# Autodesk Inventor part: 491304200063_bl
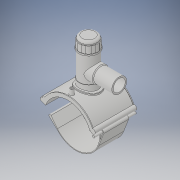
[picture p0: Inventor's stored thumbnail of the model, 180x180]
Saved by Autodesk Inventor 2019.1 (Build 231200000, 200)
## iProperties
Created: 2017-07
Part Number: 491304200063_bl
Material: Generic
Description: PLASSON TAPPING TEE SADDLE 200mm x 63mm
Document SubType Name: Modeling
Designer: KIM
Mass: 1712.7 g
Surface Area: 2671.49 cm^2
Volume: 1712.7 cm^3
Density: 1 g/cm^3
Appearance: Default
Author: KIM
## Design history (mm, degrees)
derived "491304.ipt"
feature "Solid1::491304.ipt" dims "ScaleForDerivedMember" = 10
feature "Solid2::491304.ipt" dims "ScaleForDerivedMember" = 10
feature "Solid4::491304.ipt" dims "ScaleForDerivedMember" = 10
feature "Solid5::491304.ipt" dims "ScaleForDerivedMember" = 10
tag "TaggingFeature1"
body "Solid1"
body "Solid2"
other parameters: "d1" = 101.118 [user parameter], "d2" = 284.8 [user parameter], "d4" = 176 [user parameter], "d5" = 0 [user parameter], "d6" = 0.1 [user parameter], "d8" = 0 [user parameter], "d41" = 97.65 [user parameter], "d43" = 0 [user parameter], "d45" = 0 [user parameter], "d47" = 156.159 [user parameter], "d78" = 135 [user parameter], "d79" = 15 [user parameter], "d80" = 70.4 [user parameter], "d82" = 5 deg [user parameter], "d84" = 4 [user parameter], "d85" = 14 [user parameter], "d86" = 0 [user parameter], "d87" = 3 [user parameter], "d88" = 0 [user parameter], "d97" = 3.52 [user parameter], "d98" = 0 [user parameter], "d102" = 2 [user parameter], "d120" = 140 deg [user parameter], "d123" = 606.708 [user parameter], "d126" = 0 [user parameter], "d153" = 176 [user parameter], "d154" = 0 [user parameter], "d159" = -19.7764 [user parameter], "d162" = 105.6 [user parameter], "d163" = 0 [user parameter], "d169" = 4.0905 [user parameter], "d172" = 0 [user parameter], "d173" = 1 [user parameter], "d176" = 20 deg [user parameter], "d177" = 14 [user parameter], "d180" = 0 [user parameter], "d184" = 11.2 [user parameter], "d188" = 15 [user parameter], "d189" = 14 [user parameter], "d190" = 0 [user parameter], "d195" = 90 deg [user parameter], "d197" = 0 [user parameter], "d199" = 0 [user parameter], "d200" = 14 [user parameter], "d202" = 0 [user parameter], "d203" = 195 [user parameter], "d206" = 75.6 [user parameter], "d207" = 146.25 [user parameter], "d208" = 152.1 [user parameter], "d209" = 181.35 [user parameter], "d210" = 76.86 [user parameter], "d212" = 72.45 [user parameter], "d213" = 39.15 [user parameter], "d216" = 0 [user parameter], "d219" = 2 [user parameter], "d224" = 0 [user parameter], "d259" = 50.4 [user parameter], "d260" = 63 [user parameter], "d263" = 178 [user parameter], "d265" = 0 [user parameter], "d267" = 13.00006 [user parameter], "d268" = 2.60001 [user parameter], "d269" = 2.60001 [user parameter], "d271" = 2.60001 [user parameter], "d273" = 0 [user parameter], "d274" = 23.56194 [user parameter], "d280" = 0 [user parameter], "d283" = 0 [user parameter], "d285" = 0 [user parameter], "d294" = 103 [user parameter], "d299" = 75 [user parameter], "d300" = 3 [user parameter], "d301" = 5 [user parameter], "d303" = 81.9 [user parameter], "d304" = 69.3 [user parameter], "d305" = 45 deg [user parameter], "d306" = 50.4 [user parameter], "d307" = 125 [user parameter], "d310" = 1 [user parameter], "B" = 178 [user parameter], "L" = 176 [user parameter], "d_t" = 6 [user parameter], "H2" = 195 [user parameter], "H1" = 75 [user parameter], "d_1" = 63 [user parameter]
